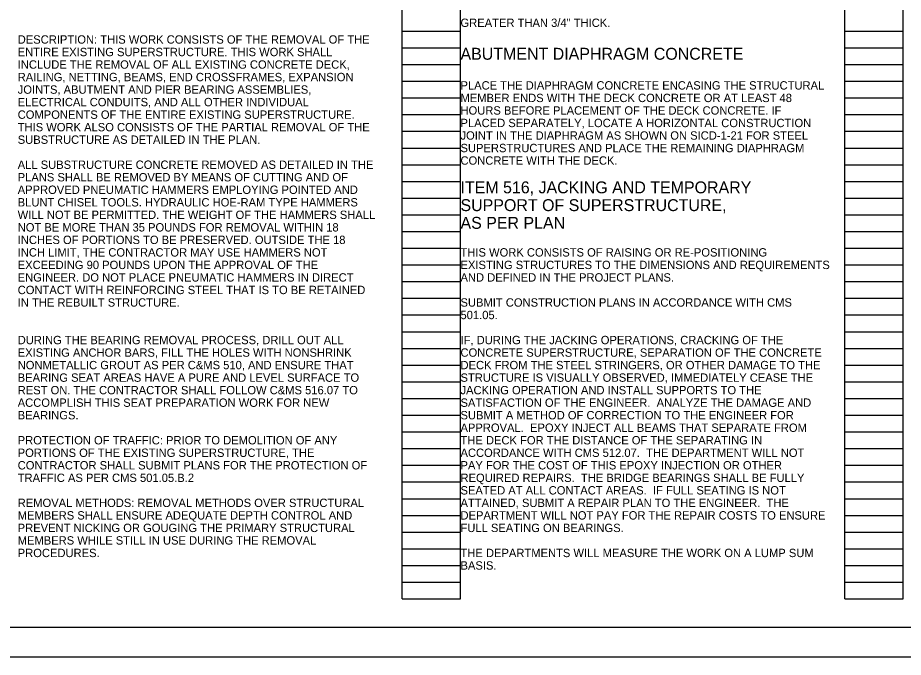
# Model space of a CAD drawing. Extents: x -51.6 to 45.5, y -38.3 to 35.3.
# Drawn here: x 10.32 to 25.16, y 0 to 10.73 of the extents above; entities that cross this region are included whole.
import ezdxf

# ---------------------------------------------------------------- set-up
doc = ezdxf.new("R2010")
doc.units = 0
for name, color, linetype in [('BD_P_Text', 7, 'Continuous'), ('SH_Border', 7, 'Continuous'), ('SH_Cut_Line', 7, 'Continuous'), ('SH_Data', 7, 'Continuous'), ('SH_Text', 7, 'Continuous')]:
    doc.layers.add(name, color=color, linetype=linetype)

msp = doc.modelspace()

# ---------------------------------------------------------------- linework, layer by layer
at = {"layer": 'SH_Border'}
msp.add_lwpolyline([(2, 21.5), (33.5, 21.5), (33.5, 0.5), (2, 0.5)], close=True, dxfattribs=at)
at = {"layer": 'SH_Cut_Line'}
msp.add_lwpolyline([(0, 22), (34, 22), (34, 0), (0, 0)], close=True, dxfattribs=at)
at = {"layer": 'SH_Data'}
for p, q in [((16.76, 0.98), (16.76, 21.14)), ((17.74, 0.98), (17.74, 21.14)), ((24.18, 0.98), (24.18, 21.14)), ((25.16, 0.98), (25.16, 21.14)), ((16.76, 10.5), (17.74, 10.5)), ((24.18, 10.5), (25.16, 10.5)), ((16.76, 10.22), (17.74, 10.22)), ((24.18, 10.22), (25.16, 10.22)), ((16.76, 9.94), (17.74, 9.94)), ((24.18, 9.94), (25.16, 9.94)), ((16.76, 9.66), (17.74, 9.66)), ((24.18, 9.66), (25.16, 9.66)), ((16.76, 9.38), (17.74, 9.38)), ((24.18, 9.38), (25.16, 9.38)), ((16.76, 9.1), (17.74, 9.1)), ((24.18, 9.1), (25.16, 9.1)), ((16.76, 8.82), (17.74, 8.82)), ((24.18, 8.82), (25.16, 8.82)), ((16.76, 8.54), (17.74, 8.54)), ((24.18, 8.54), (25.16, 8.54)), ((16.76, 8.26), (17.74, 8.26)), ((24.18, 8.26), (25.16, 8.26)), ((16.76, 7.98), (17.74, 7.98)), ((24.18, 7.98), (25.16, 7.98)), ((16.76, 7.7), (17.74, 7.7)), ((24.18, 7.7), (25.16, 7.7)), ((16.76, 7.42), (17.74, 7.42)), ((24.18, 7.42), (25.16, 7.42)), ((16.76, 7.14), (17.74, 7.14)), ((24.18, 7.14), (25.16, 7.14)), ((16.76, 6.86), (17.74, 6.86)), ((24.18, 6.86), (25.16, 6.86)), ((16.76, 6.58), (17.74, 6.58)), ((24.18, 6.58), (25.16, 6.58)), ((16.76, 6.3), (17.74, 6.3)), ((24.18, 6.3), (25.16, 6.3)), ((16.76, 6.02), (17.74, 6.02)), ((24.18, 6.02), (25.16, 6.02)), ((16.76, 5.74), (17.74, 5.74)), ((24.18, 5.74), (25.16, 5.74)), ((16.76, 5.46), (17.74, 5.46)), ((24.18, 5.46), (25.16, 5.46)), ((16.76, 5.18), (17.74, 5.18)), ((24.18, 5.18), (25.16, 5.18)), ((16.76, 4.9), (17.74, 4.9)), ((24.18, 4.9), (25.16, 4.9)), ((16.76, 4.62), (17.74, 4.62)), ((24.18, 4.62), (25.16, 4.62)), ((16.76, 4.34), (17.74, 4.34)), ((24.18, 4.34), (25.16, 4.34)), ((16.76, 4.06), (17.74, 4.06)), ((24.18, 4.06), (25.16, 4.06)), ((16.76, 3.78), (17.74, 3.78)), ((24.18, 3.78), (25.16, 3.78)), ((16.76, 3.5), (17.74, 3.5)), ((24.18, 3.5), (25.16, 3.5)), ((16.76, 3.22), (17.74, 3.22)), ((24.18, 3.22), (25.16, 3.22)), ((16.76, 2.94), (17.74, 2.94)), ((24.18, 2.94), (25.16, 2.94)), ((16.76, 2.66), (17.74, 2.66)), ((24.18, 2.66), (25.16, 2.66)), ((16.76, 2.38), (17.74, 2.38)), ((24.18, 2.38), (25.16, 2.38)), ((16.76, 2.1), (17.74, 2.1)), ((24.18, 2.1), (25.16, 2.1)), ((16.76, 1.82), (17.74, 1.82)), ((24.18, 1.82), (25.16, 1.82)), ((16.76, 1.54), (17.74, 1.54)), ((24.18, 1.54), (25.16, 1.54)), ((16.76, 1.26), (17.74, 1.26)), ((24.18, 1.26), (25.16, 1.26)), ((16.76, 0.98), (17.74, 0.98)), ((24.18, 0.98), (25.16, 0.98))]:
    msp.add_line(p, q, dxfattribs=at)

# ---------------------------------------------------------------- texts
at = {"layer": 'BD_P_Text'}
for s, height, p in [('ITEM 516, JACKING AND TEMPORARY ', 0.2, (17.74, 7.78)), ('SUPPORT OF SUPERSTRUCTURE, ', 0.2, (17.74, 7.482)), ('AS PER PLAN', 0.2, (17.74, 7.185)), ('THIS WORK CONSISTS OF RAISING OR RE-POSITIONING ', 0.14, (17.74, 6.72)), ('EXISTING STRUCTURES TO THE DIMENSIONS AND REQUIREMENTS ', 0.14, (17.74, 6.51)), ('AND DEFINED IN THE PROJECT PLANS. ', 0.14, (17.74, 6.3)), ('SUBMIT CONSTRUCTION PLANS IN ACCORDANCE WITH CMS ', 0.14, (17.74, 5.88)), ('501.05.', 0.14, (17.74, 5.67)), ('IF, DURING THE JACKING OPERATIONS, CRACKING OF THE ', 0.14, (17.74, 5.25)), ('CONCRETE SUPERSTRUCTURE, SEPARATION OF THE CONCRETE ', 0.14, (17.74, 5.04)), ('DECK FROM THE STEEL STRINGERS, OR OTHER DAMAGE TO THE ', 0.14, (17.74, 4.83)), ('STRUCTURE IS VISUALLY OBSERVED, IMMEDIATELY CEASE THE ', 0.14, (17.74, 4.62)), ('JACKING OPERATION AND INSTALL SUPPORTS TO THE ', 0.14, (17.74, 4.41)), ('SATISFACTION OF THE ENGINEER.  ANALYZE THE DAMAGE AND ', 0.14, (17.74, 4.2)), ('SUBMIT A METHOD OF CORRECTION TO THE ENGINEER FOR ', 0.14, (17.74, 3.99)), ('APPROVAL.  EPOXY INJECT ALL BEAMS THAT SEPARATE FROM ', 0.14, (17.74, 3.78)), ('THE DECK FOR THE DISTANCE OF THE SEPARATING IN ', 0.14, (17.74, 3.57)), ('ACCORDANCE WITH CMS 512.07.  THE DEPARTMENT WILL NOT ', 0.14, (17.74, 3.36)), ('PAY FOR THE COST OF THIS EPOXY INJECTION OR OTHER ', 0.14, (17.74, 3.15)), ('REQUIRED REPAIRS.  THE BRIDGE BEARINGS SHALL BE FULLY ', 0.14, (17.74, 2.94)), ('SEATED AT ALL CONTACT AREAS.  IF FULL SEATING IS NOT ', 0.14, (17.74, 2.73)), ('ATTAINED, SUBMIT A REPAIR PLAN TO THE ENGINEER.  THE ', 0.14, (17.74, 2.52)), ('DEPARTMENT WILL NOT PAY FOR THE REPAIR COSTS TO ENSURE ', 0.14, (17.74, 2.31)), ('FULL SEATING ON BEARINGS.', 0.14, (17.74, 2.1)), ('THE DEPARTMENTS WILL MEASURE THE WORK ON A LUMP SUM ', 0.14, (17.74, 1.68)), ('BASIS.', 0.14, (17.74, 1.47))]:
    msp.add_text(s, height=height, dxfattribs=at).set_placement(p)
at = {"layer": 'SH_Text'}
for s, height, p in [('GREATER THAN 3/4" THICK.', 0.14, (17.74, 10.57)), ('DESCRIPTION: THIS WORK CONSISTS OF THE REMOVAL OF THE ', 0.14, (10.32, 10.29)), ('ENTIRE EXISTING SUPERSTRUCTURE. THIS WORK SHALL ', 0.14, (10.32, 10.08)), ('ABUTMENT DIAPHRAGM CONCRETE', 0.2, (17.74, 10.02)), ('INCLUDE THE REMOVAL OF ALL EXISTING CONCRETE DECK, ', 0.14, (10.32, 9.87)), ('RAILING, NETTING, BEAMS, END CROSSFRAMES, EXPANSION ', 0.14, (10.32, 9.66)), ('PLACE THE DIAPHRAGM CONCRETE ENCASING THE STRUCTURAL ', 0.14, (17.74, 9.52)), ('JOINTS, ABUTMENT AND PIER BEARING ASSEMBLIES, ', 0.14, (10.32, 9.45)), ('ELECTRICAL CONDUITS, AND ALL OTHER INDIVIDUAL ', 0.14, (10.32, 9.24)), ('MEMBER ENDS WITH THE DECK CONCRETE OR AT LEAST 48 ', 0.14, (17.74, 9.31)), ('HOURS BEFORE PLACEMENT OF THE DECK CONCRETE. IF ', 0.14, (17.74, 9.1)), ('COMPONENTS OF THE ENTIRE EXISTING SUPERSTRUCTURE. ', 0.14, (10.32, 9.03)), ('THIS WORK ALSO CONSISTS OF THE PARTIAL REMOVAL OF THE ', 0.14, (10.32, 8.82)), ('PLACED SEPARATELY, LOCATE A HORIZONTAL CONSTRUCTION ', 0.14, (17.74, 8.89)), ('JOINT IN THE DIAPHRAGM AS SHOWN ON SICD-1-21 FOR STEEL ', 0.14, (17.74, 8.68)), ('SUBSTRUCTURE AS DETAILED IN THE PLAN.', 0.14, (10.32, 8.61)), ('SUPERSTRUCTURES AND PLACE THE REMAINING DIAPHRAGM ', 0.14, (17.74, 8.47)), ('ALL SUBSTRUCTURE CONCRETE REMOVED AS DETAILED IN THE ', 0.14, (10.32, 8.19)), ('CONCRETE WITH THE DECK.', 0.14, (17.74, 8.26)), ('PLANS SHALL BE REMOVED BY MEANS OF CUTTING AND OF ', 0.14, (10.32, 7.98)), ('APPROVED PNEUMATIC HAMMERS EMPLOYING POINTED AND ', 0.14, (10.32, 7.77)), ('BLUNT CHISEL TOOLS. HYDRAULIC HOE-RAM TYPE HAMMERS ', 0.14, (10.32, 7.56)), ('WILL NOT BE PERMITTED. THE WEIGHT OF THE HAMMERS SHALL ', 0.14, (10.32, 7.35)), ('NOT BE MORE THAN 35 POUNDS FOR REMOVAL WITHIN 18 ', 0.14, (10.32, 7.14)), ('INCHES OF PORTIONS TO BE PRESERVED. OUTSIDE THE 18 ', 0.14, (10.32, 6.93)), ('INCH LIMIT, THE CONTRACTOR MAY USE HAMMERS NOT ', 0.14, (10.32, 6.72)), ('EXCEEDING 90 POUNDS UPON THE APPROVAL OF THE ', 0.14, (10.32, 6.51)), ('ENGINEER. DO NOT PLACE PNEUMATIC HAMMERS IN DIRECT ', 0.14, (10.32, 6.3)), ('CONTACT WITH REINFORCING STEEL THAT IS TO BE RETAINED ', 0.14, (10.32, 6.09)), ('IN THE REBUILT STRUCTURE.', 0.14, (10.32, 5.88)), ('DURING THE BEARING REMOVAL PROCESS, DRILL OUT ALL ', 0.14, (10.32, 5.25)), ('EXISTING ANCHOR BARS, FILL THE HOLES WITH NONSHRINK ', 0.14, (10.32, 5.04)), ('NONMETALLIC GROUT AS PER C&MS 510, AND ENSURE THAT ', 0.14, (10.32, 4.83)), ('BEARING SEAT AREAS HAVE A PURE AND LEVEL SURFACE TO ', 0.14, (10.32, 4.62)), ('REST ON. THE CONTRACTOR SHALL FOLLOW C&MS 516.07 TO ', 0.14, (10.32, 4.41)), ('ACCOMPLISH THIS SEAT PREPARATION WORK FOR NEW ', 0.14, (10.32, 4.2)), ('BEARINGS.', 0.14, (10.32, 3.99)), ('PROTECTION OF TRAFFIC: PRIOR TO DEMOLITION OF ANY ', 0.14, (10.32, 3.57)), ('PORTIONS OF THE EXISTING SUPERSTRUCTURE, THE ', 0.14, (10.32, 3.36)), ('CONTRACTOR SHALL SUBMIT PLANS FOR THE PROTECTION OF ', 0.14, (10.32, 3.15)), ('TRAFFIC AS PER CMS 501.05.B.2', 0.14, (10.32, 2.94)), ('REMOVAL METHODS: REMOVAL METHODS OVER STRUCTURAL ', 0.14, (10.32, 2.52)), ('MEMBERS SHALL ENSURE ADEQUATE DEPTH CONTROL AND ', 0.14, (10.32, 2.31)), ('PREVENT NICKING OR GOUGING THE PRIMARY STRUCTURAL ', 0.14, (10.32, 2.1)), ('MEMBERS WHILE STILL IN USE DURING THE REMOVAL ', 0.14, (10.32, 1.89)), ('PROCEDURES.', 0.14, (10.32, 1.68))]:
    msp.add_text(s, height=height, dxfattribs=at).set_placement(p)

doc.saveas('drawing.dxf')
